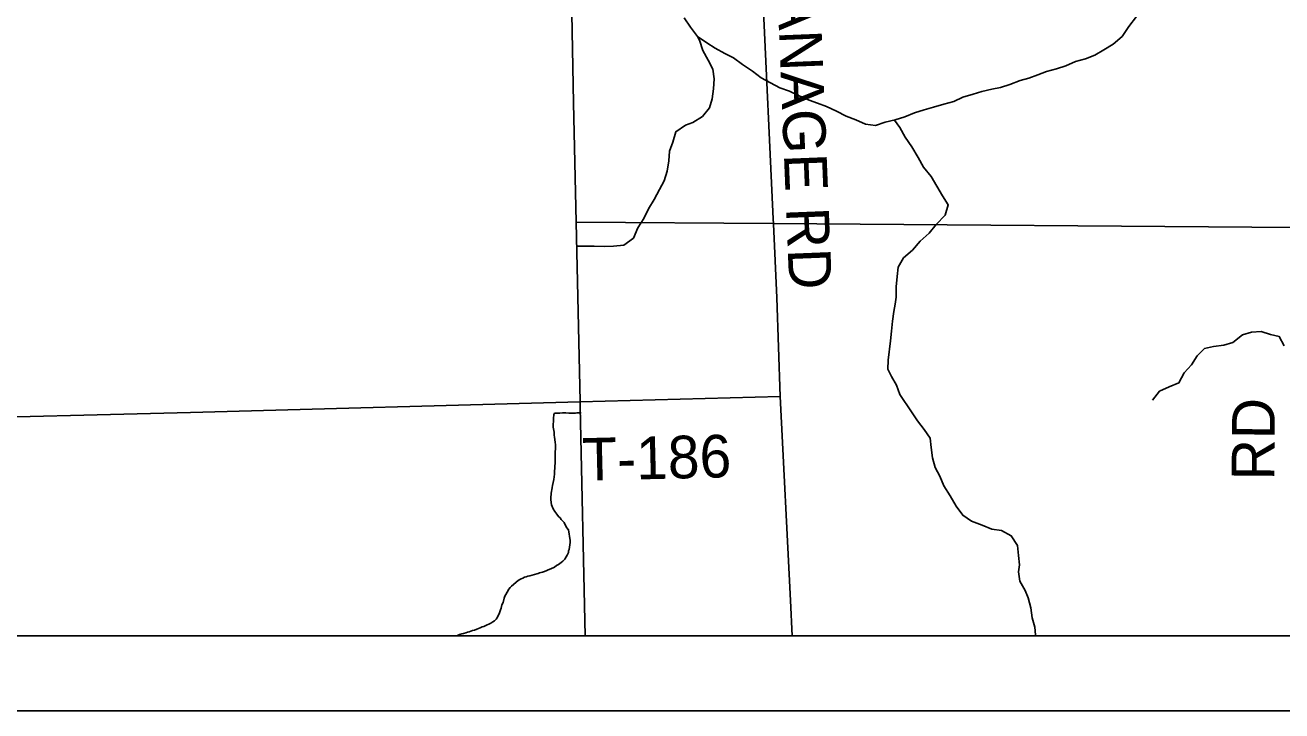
# Model space of a CAD drawing. Extents: x 0 to 34, y 0 to 22.
# Drawn here: x 6.388 to 8.061, y 14 to 14.914 of the extents above; entities that cross this region are included whole.
import ezdxf

# ---------------------------------------------------------------- set-up
doc = ezdxf.new("R2010")
doc.units = 0
for name, color, linetype in [('GM_X_Corporation', 7, 'Continuous'), ('GM_X_County_Road', 7, 'Continuous'), ('GM_X_County_Road_Text', 7, 'Continuous'), ('GM_X_Minor_River', 7, 'Continuous'), ('GM_X_Township_Road', 7, 'Continuous'), ('GM_X_Township_Road_Text', 7, 'Continuous'), ('SH_Data', 7, 'Continuous')]:
    doc.layers.add(name, color=color, linetype=linetype)

msp = doc.modelspace()

# ---------------------------------------------------------------- linework, layer by layer
at = {"layer": 'GM_X_Corporation'}
for points in [[(7.0838, 16.6084), (7.1072, 15.3824), (7.118, 14.8105), (7.1215, 14.6514), (7.1267, 14.4123), (7.1269, 14.4049), (7.1335, 14.1), (8.9, 14.1), (8.9, 20.9)], [(2.1, 20.3879), (2.1, 14.1), (7.1335, 14.1), (7.1269, 14.4049), (7.1267, 14.4123), (7.1215, 14.6514), (7.118, 14.8105), (7.1072, 15.3824), (7.0838, 16.6084)]]:
    msp.add_lwpolyline(points, dxfattribs=at)
for points in [[(8.9, 14.638), (8.9, 19.8484), (8.3424, 19.8533), (7.6795, 19.8561), (7.3272, 19.8568), (7.1717, 19.8568), (7.0046, 19.8599), (7.0077, 19.6756), (7.0107, 19.4664), (7.0305, 18.5559), (7.0429, 18.0629), (7.0494, 17.8247), (7.0577, 17.449), (7.0649, 17.2134), (7.0651, 17.204), (7.0717, 16.9849), (7.0838, 16.6084), (7.1072, 15.3824), (7.118, 14.8105), (7.1215, 14.6514), (7.384, 14.6494), (8.0793, 14.6442), (8.8452, 14.6384)], [(2.1, 15.3574), (2.1, 14.1), (7.1335, 14.1), (7.1269, 14.4049), (7.1267, 14.4123), (7.1215, 14.6514), (7.118, 14.8105), (7.1072, 15.3824), (6.0415, 15.3685), (5.8313, 15.3671), (5.1944, 15.3696), (4.1554, 15.3654), (4.1534, 15.3654), (3.4135, 15.3624), (2.6127, 15.3592)], [(7.1335, 14.1), (8.9, 14.1), (8.9, 14.638), (8.8452, 14.6384), (8.0793, 14.6442), (7.384, 14.6494), (7.1215, 14.6514), (7.1267, 14.4123), (7.1269, 14.4049)]]:
    msp.add_lwpolyline(points, close=True, dxfattribs=at)
at = {"layer": 'GM_X_County_Road'}
msp.add_line((7.3839, 14.6558), (7.3501, 15.3842), dxfattribs=at)
for points in [[(7.409, 14.1), (7.4067, 14.1471), (7.3931, 14.419), (7.3885, 14.5505), (7.3842, 14.6489), (7.3839, 14.6558)], [(6.0754, 14.3845), (6.2518, 14.3889), (6.608, 14.3975), (7.1269, 14.4117)]]:
    msp.add_lwpolyline(points, dxfattribs=at)
at = {"layer": 'GM_X_Minor_River'}
for points in [[(7.2653, 14.9237), (7.2739, 14.9114), (7.2829, 14.8987), (7.2953, 14.8902), (7.3066, 14.8832), (7.3195, 14.8761), (7.3312, 14.8702), (7.3429, 14.8613), (7.3561, 14.8524), (7.3678, 14.8435), (7.3927, 14.8305), (7.4056, 14.8258), (7.4184, 14.8195), (7.4317, 14.814), (7.443, 14.81), (7.4548, 14.8053), (7.468, 14.7994), (7.4809, 14.7927), (7.4938, 14.7879), (7.5066, 14.7817), (7.5199, 14.7803), (7.5329, 14.7847), (7.5463, 14.7879), (7.5593, 14.7915), (7.5719, 14.797), (7.5849, 14.801), (7.5975, 14.8046), (7.6113, 14.8086), (7.6243, 14.8122), (7.6366, 14.8181), (7.6503, 14.8221), (7.6618, 14.8253), (7.6752, 14.8285), (7.6866, 14.831), (7.6992, 14.8346), (7.7126, 14.8401), (7.7241, 14.8434), (7.7363, 14.8478), (7.7478, 14.8522), (7.7612, 14.8558), (7.7734, 14.8597), (7.7865, 14.8656), (7.7998, 14.8689), (7.8121, 14.874), (7.8244, 14.881), (7.8367, 14.8885), (7.8486, 14.8989), (7.8575, 14.9121), (7.8676, 14.9252)], [(7.2829, 14.8987), (7.2855, 14.8938), (7.2902, 14.88), (7.2973, 14.8673), (7.3036, 14.8551), (7.3053, 14.8425), (7.3043, 14.8288), (7.3026, 14.8159), (7.2991, 14.8038), (7.2898, 14.7922), (7.2767, 14.784), (7.2671, 14.7804), (7.2544, 14.7718), (7.2501, 14.7578), (7.2457, 14.7461), (7.2448, 14.7332), (7.2427, 14.7195), (7.2387, 14.7063), (7.2324, 14.6949), (7.2254, 14.6817), (7.218, 14.6689), (7.2117, 14.6561), (7.2036, 14.6437), (7.198, 14.6301), (7.185, 14.6208), (7.1712, 14.6195), (7.159, 14.6189), (7.1453, 14.6195), (7.1232, 14.6192)], [(7.5453, 14.7877), (7.5455, 14.7874), (7.5526, 14.7775), (7.5597, 14.7645), (7.5686, 14.7515), (7.5768, 14.7376), (7.5839, 14.7246), (7.5944, 14.7123), (7.6092, 14.6862), (7.6171, 14.6743), (7.6127, 14.6607), (7.6011, 14.6483), (7.5914, 14.6367), (7.5798, 14.6258), (7.5694, 14.6142), (7.5574, 14.6037), (7.5504, 14.5913), (7.5491, 14.5788), (7.5478, 14.5651), (7.5476, 14.5514), (7.5463, 14.5419), (7.5443, 14.5324), (7.5426, 14.5192), (7.5412, 14.5059), (7.5403, 14.4933), (7.5369, 14.4675), (7.5367, 14.4554), (7.5415, 14.4458), (7.5479, 14.4343), (7.5523, 14.4217), (7.5679, 14.3986), (7.5761, 14.3864), (7.5851, 14.3748), (7.5929, 14.3633), (7.5943, 14.3511), (7.596, 14.3374), (7.5996, 14.3244), (7.6056, 14.3129), (7.6111, 14.2999), (7.6197, 14.2868), (7.6275, 14.273), (7.6364, 14.2607), (7.6481, 14.253), (7.6621, 14.2474), (7.675, 14.2423), (7.6879, 14.2402), (7.7008, 14.2335), (7.7094, 14.2205), (7.7107, 14.2071), (7.712, 14.1946), (7.7104, 14.1851), (7.7121, 14.1729), (7.7196, 14.1603), (7.7232, 14.1507), (7.7269, 14.1373), (7.7286, 14.124), (7.7322, 14.1114), (7.7332, 14.1015), (7.7331, 14.1)], [(8.0645, 14.4865), (8.0578, 14.4988), (8.046, 14.5017), (8.0339, 14.5056), (8.0209, 14.5047), (8.0087, 14.5011), (7.996, 14.491), (7.9838, 14.4874), (7.9704, 14.4857), (7.9582, 14.4828), (7.9485, 14.4731), (7.9411, 14.461), (7.9311, 14.4505), (7.9241, 14.4373), (7.911, 14.4318), (7.8984, 14.426), (7.8891, 14.4143)], [(7.128, 14.3974), (7.1226, 14.3973), (7.1207, 14.3969), (7.118, 14.3966), (7.1146, 14.3966), (7.1115, 14.3966), (7.1077, 14.397), (7.105, 14.397), (7.1031, 14.397), (7.0997, 14.3967), (7.0955, 14.3967), (7.0928, 14.3967), (7.0917, 14.3948), (7.0913, 14.3895), (7.0908, 14.3781), (7.092, 14.3716), (7.0923, 14.3671), (7.0927, 14.3652), (7.093, 14.3614), (7.0934, 14.3579), (7.0938, 14.3545), (7.0938, 14.3519), (7.0933, 14.3424), (7.0933, 14.3359), (7.0937, 14.3328), (7.0932, 14.3233), (7.0928, 14.3195), (7.0928, 14.3154), (7.0916, 14.3085), (7.0901, 14.3005), (7.0897, 14.2979), (7.0889, 14.2945), (7.0885, 14.2926), (7.0881, 14.2899), (7.0881, 14.288), (7.0877, 14.2857), (7.0877, 14.2835), (7.0877, 14.2812), (7.0888, 14.2747), (7.0907, 14.2694), (7.0929, 14.2659), (7.0956, 14.2621), (7.0978, 14.259), (7.1001, 14.2571), (7.1016, 14.2552), (7.1035, 14.2529), (7.1054, 14.251), (7.1088, 14.2445), (7.1111, 14.2415), (7.1133, 14.227), (7.1133, 14.2243), (7.1121, 14.2152), (7.1113, 14.2133), (7.1113, 14.211), (7.1094, 14.2076), (7.1082, 14.2054), (7.1063, 14.202), (7.1036, 14.1997), (7.1013, 14.1978), (7.0979, 14.1952), (7.0952, 14.1937), (7.0925, 14.1914), (7.0876, 14.1895), (7.0841, 14.188), (7.0822, 14.1873), (7.0795, 14.1858), (7.0765, 14.185), (7.0746, 14.1843), (7.0727, 14.1839), (7.0708, 14.1832), (7.0689, 14.1828), (7.0658, 14.1817), (7.0628, 14.181), (7.0597, 14.1802), (7.057, 14.1795), (7.0551, 14.1787), (7.0525, 14.178), (7.0506, 14.1769), (7.0483, 14.1761), (7.0463, 14.175), (7.0444, 14.1739), (7.0353, 14.1663), (7.0337, 14.1644), (7.0318, 14.1621), (7.0295, 14.158), (7.028, 14.1553), (7.0264, 14.1531), (7.0257, 14.1504), (7.0241, 14.1443), (7.0226, 14.1413), (7.0218, 14.1371), (7.0206, 14.1348), (7.0198, 14.1322), (7.0191, 14.1292), (7.0175, 14.1269), (7.0164, 14.1242), (7.0148, 14.1223), (7.0125, 14.1201), (7.0106, 14.1186), (7.008, 14.1167), (7.0053, 14.1156)], [(7.0053, 14.1156), (7.003, 14.1148), (7.0003, 14.1133), (6.9984, 14.1126), (6.9965, 14.1118), (6.9938, 14.1107), (6.9915, 14.1099), (6.9892, 14.1088), (6.9862, 14.1077), (6.9835, 14.107), (6.9812, 14.1062), (6.9789, 14.1055), (6.9767, 14.1047), (6.9744, 14.104), (6.9713, 14.1032), (6.969, 14.1025), (6.9663, 14.1017), (6.9633, 14.1006), (6.9622, 14.1)]]:
    msp.add_lwpolyline(points, dxfattribs=at)
at = {"layer": 'GM_X_Township_Road'}
msp.add_line((7.1269, 14.4117), (7.3931, 14.419), dxfattribs=at)
at = {"layer": 'SH_Data'}
for p, q in [((2.1, 14.1), (8.9, 14.1)), ((2, 14), (9, 14))]:
    msp.add_line(p, q, dxfattribs=at)

# ---------------------------------------------------------------- texts
at = {"layer": 'GM_X_County_Road_Text'}
msp.add_text('GORE ORPHANAGE RD', height=0.056818, rotation=272.2962, dxfattribs=at).set_placement((7.3709, 15.4211))
at = {"layer": 'GM_X_Township_Road_Text'}
for s, rotation, p in [('RD', 89.5063, (8.0511, 14.307)), ('T-186', 1.4033, (7.1302, 14.3066))]:
    msp.add_text(s, height=0.05682, rotation=rotation, dxfattribs=at).set_placement(p)

doc.saveas('drawing.dxf')
